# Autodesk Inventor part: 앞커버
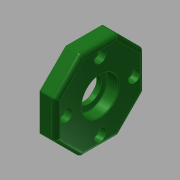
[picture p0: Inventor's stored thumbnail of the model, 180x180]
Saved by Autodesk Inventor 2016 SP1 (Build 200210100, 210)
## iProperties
Created: 2015-11
Part Number: 앞커버
Material: 알루미늄 6061
Document SubType Name: Modeling
Designer: mduedu
Density: 1 g/cm^3
Appearance: 매끄러움 - 짙은 산림 녹색
Author: mduedu
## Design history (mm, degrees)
sketch "스케치5" dims "d66" = 60
  geometry: L1 (12.426, 30)-(30, 12.426); L2 (30, 12.426)-(30, -12.426); L3 (30, -12.426)-(12.426, -30); L4 (12.426, -30)-(-12.426, -30); L5 (-12.426, -30)-(-30, -12.426); L6 (-30, -12.426)-(-30, 12.426); L7 (-30, 12.426)-(-12.426, 30); L8 (-12.426, 30)-(12.426, 30); 4 further points
  constraints: 16 end point, 2 coincident, 2 vertical alignment, 1 midpoint, 19 other
extrude "돌출2" new body sketch "스케치5" distance "d67" = 11; taper "d68" = 0 deg
sketch "스케치6"
  geometry: C1 r 16 at (0, 0); 1 further point
  constraints: 1 centre point, 1 coincident
  dimensions: "d69" = 32 diameter of C1
extrude "돌출3" join sketch "스케치6" distance "d70" = 3; taper "d71" = 0 deg
hole "구멍7" diameter "d98" = 25; stored, may be unused: countersink angle "d102" = 90 deg, drill point angle "d104" = 0 deg; dims "d96" = 10, "d97" = 10, "d99" = 6, "d100" = 4, "d101" = 2, "d103" = 3
hole "구멍8" diameter "d107" = 25; stored, may be unused: countersink angle "d111" = 90 deg, drill point angle "d113" = 0 deg; dims "d105" = 10, "d106" = 10, "d108" = 6, "d109" = 4, "d110" = 2, "d112" = 7.7
hole "구멍9" diameter "d116" = 17; stored, may be unused: countersink angle "d120" = 90 deg, drill point angle "d122" = 0 deg; dims "d114" = 10, "d115" = 10, "d117" = 6, "d118" = 4, "d119" = 2, "d121" = 7.7
chamfer "모따기2" distance "d123" = 0.6; stored, may be unused: second distance "d124" = 2, angle "d125" = 30 deg
fillet "모깎기11" dims "d126" = 0.3
fillet "모깎기12" dims "d127" = 1
fillet "모깎기13" dims "d128" = 3
fillet "모깎기14" dims "d129" = 3
fillet "모깎기15" dims "d130" = 0.3
sketch "스케치8" dims "d131" = 46
  geometry: 3 further points
  constraints: 2 vertical alignment, 1 coincident, 2 other
hole "구멍10" sketch "스케치8" at (0, 23) diameter "d132" = 4.5; stored, may be unused: countersink angle "d136" = 90 deg, drill point angle "d138" = 0 deg; dims "d133" = 6, "d134" = 8, "d135" = 4.6, "d137" = 7.7
node "솔리드2"
pattern_circular "원형 패턴4" dims angle "d140" = 360 deg
